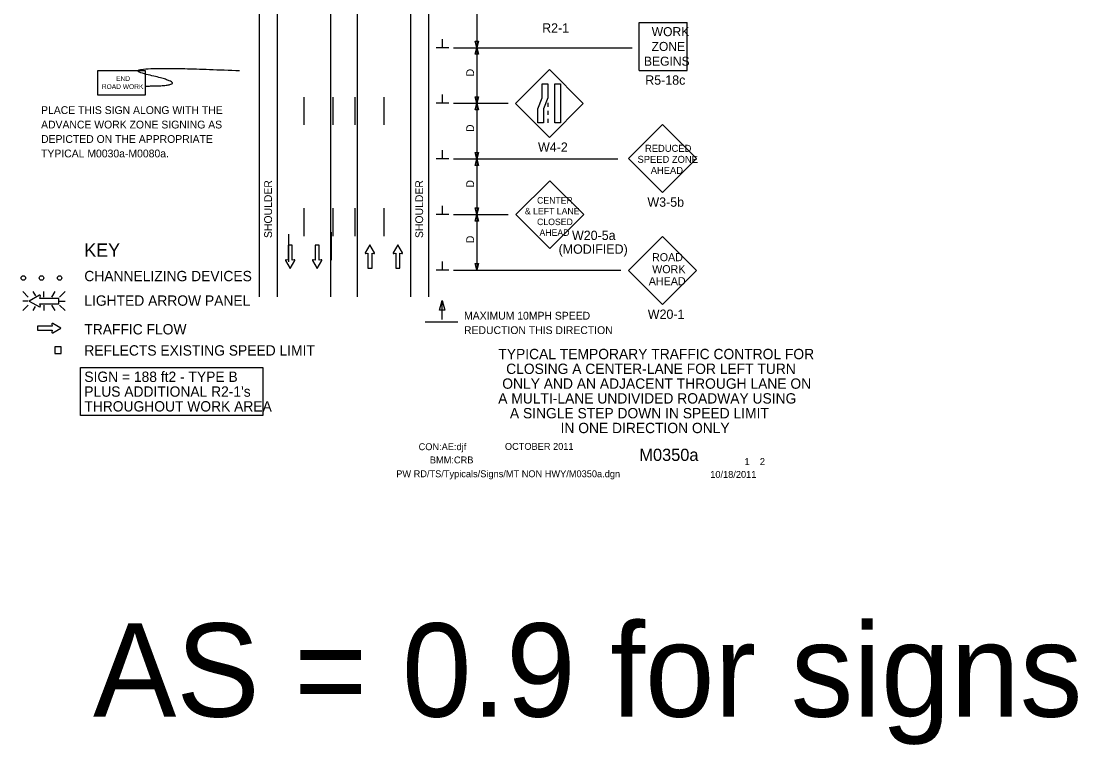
# Model space of a CAD drawing. Extents: x 16733 to 18475, y 5693 to 6915.
# Drawn here: x 16733 to 17684, y 5693 to 6344 of the extents above; entities that cross this region are included whole.
import ezdxf

# ---------------------------------------------------------------- set-up
doc = ezdxf.new("R2010")
doc.units = 0
for name, color, linetype in [('ALI_LEGAL_EX', 7, 'Continuous'), ('BORDER_SIGNAL_WO', 7, 'Continuous'), ('MT_SCRATCH_LEVEL_E', 7, 'Continuous'), ('PAVT_EDGE_EX', 7, 'Continuous'), ('TRAFFIC_SIGNS_PR', 7, 'Continuous'), ('TYPICAL_TEXT_DIMEN_EX', 7, 'Continuous'), ('TYPICAL_TEXT_DIMEN_PR', 7, 'Continuous')]:
    doc.layers.add(name, color=color, linetype=linetype)

msp = doc.modelspace()

# ---------------------------------------------------------------- linework, layer by layer
at = {"layer": 'ALI_LEGAL_EX'}
for points in [[(16987.43, 6275.6), (16987.43, 6250.6)], [(17013.43, 6275.6), (17013.43, 6250.6)], [(17033.43, 6275.6), (17033.43, 6250.6)], [(17059.43, 6275.6), (17059.43, 6250.6)], [(16987.43, 6175.6), (16987.43, 6150.6)], [(17013.43, 6175.6), (17013.43, 6150.6)], [(17033.43, 6175.6), (17033.43, 6150.6)], [(17059.43, 6175.6), (17059.43, 6150.6)]]:
    msp.add_lwpolyline(points, dxfattribs=at)
at = {"layer": 'MT_SCRATCH_LEVEL_E'}
for p, q in [((16977.1, 6142.27), (16973.36, 6142.27)), ((16973.36, 6142.27), (16973.36, 6129.01)), ((16977.1, 6142.27), (16973.36, 6142.27)), ((16973.36, 6142.27), (16973.36, 6129.01)), ((16977.1, 6129.01), (16977.1, 6142.27)), ((16977.1, 6129.01), (16977.1, 6142.27)), ((17001.36, 6142.27), (16997.62, 6142.27)), ((16997.62, 6142.27), (16997.62, 6129.01)), ((17001.36, 6142.27), (16997.62, 6142.27)), ((16997.62, 6142.27), (16997.62, 6129.01)), ((17001.36, 6129.01), (17001.36, 6142.27)), ((17001.36, 6129.01), (17001.36, 6142.27)), ((17046.87, 6142.73), (17042.76, 6135.49)), ((17046.87, 6142.73), (17042.76, 6135.49)), ((17051.02, 6135.49), (17046.87, 6142.73)), ((17051.02, 6135.49), (17046.87, 6142.73)), ((17071.96, 6142.73), (17067.85, 6135.49)), ((17071.96, 6142.73), (17067.85, 6135.49)), ((17076.11, 6135.49), (17071.96, 6142.73)), ((17076.11, 6135.49), (17071.96, 6142.73)), ((17043.24, 6134.81), (17045.02, 6135.12)), ((17043.24, 6134.81), (17045.02, 6135.12)), ((17045.02, 6135.12), (17045.02, 6121.86)), ((17045.02, 6135.12), (17045.02, 6121.86)), ((17048.76, 6121.86), (17048.76, 6135.12)), ((17048.76, 6135.12), (17050.54, 6134.81)), ((17048.76, 6121.86), (17048.76, 6135.12)), ((17048.76, 6135.12), (17050.54, 6134.81)), ((17068.33, 6134.81), (17070.11, 6135.12)), ((17068.33, 6134.81), (17070.11, 6135.12)), ((17070.11, 6135.12), (17070.11, 6121.86)), ((17070.11, 6135.12), (17070.11, 6121.86)), ((17073.85, 6121.86), (17073.85, 6135.12)), ((17073.85, 6135.12), (17075.63, 6134.81)), ((17073.85, 6121.86), (17073.85, 6135.12)), ((17073.85, 6135.12), (17075.63, 6134.81)), ((16971.1, 6128.64), (16975.25, 6121.4)), ((16971.1, 6128.64), (16975.25, 6121.4)), ((16973.36, 6129.01), (16971.58, 6129.33)), ((16973.36, 6129.01), (16971.58, 6129.33)), ((16975.25, 6121.4), (16979.36, 6128.64)), ((16975.25, 6121.4), (16979.36, 6128.64)), ((16978.88, 6129.33), (16977.1, 6129.01)), ((16978.88, 6129.33), (16977.1, 6129.01)), ((16995.36, 6128.64), (16999.51, 6121.4)), ((16995.36, 6128.64), (16999.51, 6121.4)), ((16997.62, 6129.01), (16995.84, 6129.33)), ((16997.62, 6129.01), (16995.84, 6129.33)), ((16999.51, 6121.4), (17003.62, 6128.64)), ((16999.51, 6121.4), (17003.62, 6128.64)), ((17003.14, 6129.33), (17001.36, 6129.01)), ((17003.14, 6129.33), (17001.36, 6129.01)), ((17045.02, 6121.86), (17048.76, 6121.86)), ((17045.02, 6121.86), (17048.76, 6121.86)), ((17070.11, 6121.86), (17073.85, 6121.86)), ((17070.11, 6121.86), (17073.85, 6121.86)), ((16761.23, 6069.6), (16747.97, 6069.6)), ((16747.97, 6069.6), (16747.97, 6065.86)), ((16761.23, 6069.6), (16747.97, 6069.6)), ((16747.97, 6069.6), (16747.97, 6065.86)), ((16747.97, 6065.86), (16761.23, 6065.86)), ((16747.97, 6065.86), (16761.23, 6065.86)), ((16760.91, 6071.38), (16761.23, 6069.6)), ((16760.91, 6071.38), (16761.23, 6069.6)), ((16761.23, 6065.86), (16760.91, 6064.08)), ((16761.23, 6065.86), (16760.91, 6064.08)), ((16768.84, 6067.75), (16761.6, 6071.86)), ((16768.84, 6067.75), (16761.6, 6071.86)), ((16761.6, 6063.6), (16768.84, 6067.75)), ((16761.6, 6063.6), (16768.84, 6067.75))]:
    msp.add_line(p, q, dxfattribs=at)
for centre, start, end in [((17043.17, 6135.26), 150.42484, 279.96381), ((17043.17, 6135.26), 150.42484, 279.96381), ((17050.61, 6135.27), 260.03619, 29.77312), ((17050.61, 6135.27), 260.03619, 29.77312), ((17068.26, 6135.26), 150.42484, 279.96381), ((17068.26, 6135.26), 150.42484, 279.96381), ((17075.7, 6135.27), 260.03619, 29.77312), ((17075.7, 6135.27), 260.03619, 29.77312), ((16971.51, 6128.87), 80.03619, 209.77312), ((16971.51, 6128.87), 80.03619, 209.77312), ((16978.96, 6128.87), 330.42484, 99.96381), ((16978.96, 6128.87), 330.42484, 99.96381), ((16995.77, 6128.87), 80.03619, 209.77312), ((16995.77, 6128.87), 80.03619, 209.77312), ((17003.21, 6128.87), 330.42484, 99.96381), ((17003.21, 6128.87), 330.42484, 99.96381), ((16761.37, 6071.45), 60.42484, 189.96381), ((16761.37, 6071.45), 60.42484, 189.96381), ((16761.37, 6064.01), 170.03619, 299.77312), ((16761.37, 6064.01), 170.03619, 299.77312)]:
    msp.add_arc(centre, 0.463, start, end, dxfattribs=at)
at = {"layer": 'PAVT_EDGE_EX'}
for p, q in [((16947.43, 6893.09), (16947.43, 6095.81)), ((16963.43, 6893.09), (16963.43, 6095.81)), ((17011.43, 6893.09), (17011.43, 6095.81)), ((17035.43, 6893.09), (17035.43, 6095.81)), ((17083.43, 6893.09), (17083.43, 6095.81)), ((17099.43, 6893.09), (17099.43, 6095.81))]:
    msp.add_line(p, q, dxfattribs=at)
for points in [[(16974.07, 6127.31), (16974.07, 6152.31)], [(17012.43, 6129.06), (17012.43, 6154.06)]]:
    msp.add_lwpolyline(points, dxfattribs=at)
at = {"layer": 'TRAFFIC_SIGNS_PR'}
for p, q in [((17289.06, 6299.56), (17289.06, 6342.76)), ((17289.06, 6342.76), (17332.26, 6342.76)), ((17332.26, 6299.56), (17332.26, 6342.76)), ((17208.25, 6300.35), (17177.7, 6269.81)), ((17238.79, 6269.81), (17208.25, 6300.35)), ((17289.06, 6299.56), (17332.26, 6299.56)), ((17177.7, 6269.81), (17208.25, 6239.26)), ((17206.84, 6270.36), (17206.84, 6266.76)), ((17206.84, 6263.16), (17206.84, 6259.56)), ((17208.25, 6239.26), (17238.79, 6269.81)), ((17206.84, 6255.96), (17206.84, 6252.36)), ((17310, 6250.91), (17279.45, 6220.36)), ((17340.55, 6220.36), (17310, 6250.91)), ((17279.45, 6220.36), (17310, 6189.82)), ((17310, 6189.82), (17340.55, 6220.36)), ((17208.7, 6200.38), (17178.15, 6169.83)), ((17239.25, 6169.83), (17208.7, 6200.38)), ((17178.15, 6169.83), (17208.7, 6139.29)), ((17208.7, 6139.29), (17239.25, 6169.83)), ((17310.1, 6150.08), (17279.55, 6119.53)), ((17340.65, 6119.53), (17310.1, 6150.08)), ((17279.55, 6119.53), (17310.1, 6088.99)), ((17310.1, 6088.99), (17340.65, 6119.53)), ((16734.59, 6100.62), (16739.53, 6095.69)), ((16739.53, 6092.13), (16734.59, 6092.13)), ((16746.35, 6096.8), (16744.15, 6100.62)), ((16753.67, 6095.69), (16753.67, 6100.62)), ((16760.91, 6095.69), (16763.76, 6100.62)), ((16767.82, 6095.69), (16772.76, 6100.62)), ((16767.82, 6092.13), (16772.76, 6092.13)), ((16734.59, 6083.64), (16739.53, 6088.58)), ((16744.1, 6083.64), (16746.22, 6087.3)), ((16753.67, 6088.58), (16753.67, 6083.64)), ((16763.8, 6083.64), (16760.95, 6088.58)), ((16767.82, 6088.58), (16772.76, 6083.64))]:
    msp.add_line(p, q, dxfattribs=at)
for points in [[(16801.74, 6277.49), (16844.94, 6277.49), (16844.94, 6299.09), (16801.74, 6299.09)], [(17206.84, 6287.51), (17206.84, 6274.93), (17203.08, 6264.94), (17203.08, 6252.36), (17198.02, 6252.36), (17198.02, 6264.94), (17201.79, 6274.93), (17201.79, 6287.51)], [(17218.25, 6287.51), (17218.25, 6252.36), (17213.19, 6252.36), (17213.19, 6287.51)], [(16763.53, 6044.94), (16769.13, 6044.94), (16769.13, 6051.11), (16763.53, 6051.11)]]:
    msp.add_lwpolyline(points, close=True, dxfattribs=at)
for points in [[(16749.6, 6097.41), (16740.31, 6092.13), (16749.6, 6086.81)], [(16750.48, 6087.44), (16750.08, 6089.71), (16767.09, 6089.71), (16767.09, 6094.51), (16750.08, 6094.51), (16750.48, 6096.79)]]:
    msp.add_lwpolyline(points, dxfattribs=at)
for centre in [(16735.21, 6112.91), (16751.51, 6112.91), (16767.81, 6112.91)]:
    msp.add_circle(centre, 2, dxfattribs=at)
for centre, radius, start, end in [((16749.89, 6096.88), 0.598, 350.73078, 118.89165), ((16749.89, 6087.33), 0.597, 241.48329, 9.95933)]:
    msp.add_arc(centre, radius, start, end, dxfattribs=at)
msp.add_open_spline([(16844.42, 6285.5), (16891.66, 6285.5), (16806.64, 6304.85), (16929.73, 6299.36)], degree=2, dxfattribs=at)
at = {"layer": 'TYPICAL_TEXT_DIMEN_EX'}
msp.add_lwpolyline([(16786.71, 6032.52), (16950.7, 6032.52), (16950.7, 5989.16), (16786.71, 5989.16)], close=True, dxfattribs=at)
at = {"layer": 'TYPICAL_TEXT_DIMEN_PR'}
for p, q in [((17143.07, 6369.97), (17143.07, 6319.97)), ((17117.82, 6319.97), (17106.57, 6319.97)), ((17112.19, 6319.97), (17112.19, 6327.75)), ((17122.07, 6319.97), (17282.71, 6319.97)), ((17143.07, 6319.97), (17141.5, 6325.83)), ((17141.5, 6325.83), (17143.07, 6325.83)), ((17141.5, 6314.11), (17143.07, 6319.97)), ((17143.07, 6325.83), (17144.64, 6325.83)), ((17144.64, 6325.83), (17143.07, 6319.97)), ((17143.07, 6319.97), (17143.07, 6269.97)), ((17143.07, 6319.97), (17144.64, 6314.11)), ((17143.07, 6314.11), (17141.5, 6314.11)), ((17144.64, 6314.11), (17143.07, 6314.11)), ((17112.19, 6269.97), (17112.19, 6277.75)), ((17143.07, 6269.97), (17141.5, 6275.83)), ((17141.5, 6275.83), (17143.07, 6275.83)), ((17143.07, 6275.83), (17144.64, 6275.83)), ((17144.64, 6275.83), (17143.07, 6269.97)), ((17117.82, 6269.97), (17106.57, 6269.97)), ((17122.07, 6269.97), (17171.13, 6269.97)), ((17141.5, 6264.11), (17143.07, 6269.97)), ((17143.07, 6264.11), (17141.5, 6264.11)), ((17143.07, 6269.97), (17143.07, 6219.97)), ((17143.07, 6269.97), (17144.64, 6264.11)), ((17144.64, 6264.11), (17143.07, 6264.11)), ((17112.19, 6219.97), (17112.19, 6227.75)), ((17143.07, 6219.97), (17141.5, 6225.83)), ((17141.5, 6225.83), (17143.07, 6225.83)), ((17143.07, 6225.83), (17144.64, 6225.83)), ((17144.64, 6225.83), (17143.07, 6219.97)), ((17117.82, 6219.97), (17106.57, 6219.97)), ((17122.07, 6219.97), (17269.94, 6219.97)), ((17141.5, 6214.11), (17143.07, 6219.97)), ((17143.07, 6219.97), (17143.07, 6169.97)), ((17143.07, 6219.97), (17144.64, 6214.11)), ((17143.07, 6214.11), (17141.5, 6214.11)), ((17144.64, 6214.11), (17143.07, 6214.11)), ((17112.19, 6169.97), (17112.19, 6177.75)), ((17117.82, 6169.97), (17106.57, 6169.97)), ((17122.07, 6169.97), (17171.13, 6169.97)), ((17143.07, 6169.97), (17141.5, 6175.83)), ((17141.5, 6175.83), (17143.07, 6175.83)), ((17141.5, 6164.11), (17143.07, 6169.97)), ((17143.07, 6175.83), (17144.64, 6175.83)), ((17144.64, 6175.83), (17143.07, 6169.97)), ((17143.07, 6169.97), (17143.07, 6119.97)), ((17143.07, 6169.97), (17144.64, 6164.11)), ((17143.07, 6164.11), (17141.5, 6164.11)), ((17144.64, 6164.11), (17143.07, 6164.11)), ((17112.19, 6119.97), (17112.19, 6127.75)), ((17143.07, 6119.97), (17141.5, 6125.83)), ((17141.5, 6125.83), (17143.07, 6125.83)), ((17143.07, 6125.83), (17144.64, 6125.83)), ((17144.64, 6125.83), (17143.07, 6119.97)), ((17117.82, 6119.97), (17106.57, 6119.97)), ((17122.07, 6119.97), (17272.51, 6119.97)), ((17109.5, 6083.88), (17111.86, 6092.68)), ((17111.86, 6075.55), (17111.86, 6092.68)), ((17111.86, 6092.68), (17114.22, 6083.88)), ((17111.86, 6083.88), (17109.5, 6083.88)), ((17114.22, 6083.88), (17111.86, 6083.88)), ((17126.03, 6073.05), (17096.59, 6073.05))]:
    msp.add_line(p, q, dxfattribs=at)

# ---------------------------------------------------------------- texts
at = {"layer": 'BORDER_SIGNAL_WO'}
for s, height, p in [('TYPICAL TEMPORARY TRAFFIC CONTROL FOR', 9.3, (17162.4, 6039.87)), ('CLOSING A CENTER-LANE FOR LEFT TURN', 9.3, (17169.41, 6026.57)), ('ONLY AND AN ADJACENT THROUGH LANE ON', 9.3, (17165.91, 6013.27)), ('A MULTI-LANE UNDIVIDED ROADWAY USING ', 9.3, (17162.28, 5999.97)), ('A SINGLE STEP DOWN IN SPEED LIMIT ', 9.3, (17172.78, 5986.67)), ('IN ONE DIRECTION ONLY', 9.3, (17218.35, 5973.37)), ('CON:AE:djf', 6.2, (17090.69, 5958.06)), ('    OCTOBER 2011    ', 6.2, (17159.08, 5958.34)), ('    M0350a   ', 11, (17272.86, 5948.38)), ('BMM:CRB   ', 6.2, (17100.81, 5946.17)), (' 1    2 ', 6.2, (17381.45, 5944.7)), ('PW RD/TS/Typicals/Signs/MT NON HWY/M0350a.dgn     ', 6.2, (17070.55, 5933.71)), ('10/18/2011    ', 6.2, (17352.93, 5933.13))]:
    msp.add_text(s, height=height, dxfattribs=at).set_placement(p)
at = {"layer": 'TRAFFIC_SIGNS_PR'}
for s, height, p in [('R2-1', 8.37, (17201.78, 6333.55)), ('WORK', 8.119, (17300.31, 6330.35)), ('ZONE', 8.119, (17300.18, 6317.06)), ('BEGINS', 8.119, (17293.35, 6303.78)), ('END', 4.31, (16818.61, 6290.02)), ('R5-18c', 8.37, (17294.48, 6286.69)), ('ROAD WORK', 4.31, (16805.8, 6282.83)), ('PLACE THIS SIGN ALONG WITH THE', 7, (16751.15, 6260.35)), ('ADVANCE WORK ZONE SIGNING AS', 7, (16751.15, 6247.35)), ('DEPICTED ON THE APPROPRIATE', 7, (16751.15, 6234.35)), ('W4-2', 8.37, (17198.07, 6226.39)), ('TYPICAL M0030a-M0080a.', 7, (16751.15, 6221.35)), ('REDUCED', 6.3, (17294.32, 6226.33)), ('SPEED ZONE', 6.3, (17287.56, 6216.43)), ('AHEAD', 6.3, (17299.44, 6206.53)), ('CENTER', 5.85, (17197.2, 6179.78)), ('W3-5b', 8.37, (17296.45, 6176.95)), ('& LEFT LANE', 5.85, (17186.25, 6170.11)), ('CLOSED', 5.85, (17197.21, 6160.43)), ('AHEAD', 5.85, (17199.39, 6150.76)), ('W20-5a', 8.37, (17228.62, 6147.04)), ('(MODIFIED)', 8.37, (17216.58, 6134.67)), ('ROAD', 7.2, (17300.58, 6128.01)), ('WORK', 7.2, (17300.71, 6117.21)), ('AHEAD', 7.2, (17297.68, 6106.41)), ('W20-1', 8.37, (17296.79, 6076.12))]:
    msp.add_text(s, height=height, dxfattribs=at).set_placement(p)
at = {"layer": 'TYPICAL_TEXT_DIMEN_EX'}
for s, height, p in [('KEY', 12, (16790.05, 6132.02)), ('CHANNELIZING DEVICES', 9.3, (16790.05, 6109.97)), ('LIGHTED ARROW PANEL', 9.3, (16790.05, 6087.92)), ('TRAFFIC FLOW', 9.3, (16790.05, 6062.12)), ('REFLECTS EXISTING SPEED LIMIT', 9.3, (16790.05, 6043.1)), ('SIGN = 188 ft2 - TYPE B', 9.3, (16790.05, 6019.41)), ("PLUS ADDITIONAL R2-1's", 9.3, (16790.05, 6006.11)), ('THROUGHOUT WORK AREA', 9.3, (16790.05, 5992.81))]:
    msp.add_text(s, height=height, dxfattribs=at).set_placement(p)
at = {"layer": 'TYPICAL_TEXT_DIMEN_PR'}
for s, p in [('D', (17140.51, 6294.19)), ('D', (17140.51, 6294.19)), ('D', (17140.51, 6244.19)), ('SHOULDER', (16958.81, 6148.84)), ('SHOULDER', (17094.71, 6148.84)), ('D', (17140.51, 6194.19)), ('D', (17140.51, 6144.19))]:
    msp.add_text(s, height=7, rotation=90, dxfattribs=at).set_placement(p)
for s, height, p in [('MAXIMUM 10MPH SPEED', 7, (17131.55, 6075.47)), ('REDUCTION THIS DIRECTION', 7, (17131.55, 6062.47)), ('AS = 0.9 for signs', 84, (16797.89, 5718.39))]:
    msp.add_text(s, height=height, dxfattribs=at).set_placement(p)

doc.saveas('drawing.dxf')
